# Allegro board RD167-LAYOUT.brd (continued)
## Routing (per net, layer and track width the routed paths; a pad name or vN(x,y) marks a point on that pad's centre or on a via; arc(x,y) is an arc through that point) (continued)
N15598095: length 6.9
  BOTTOM w0.5: 124,238 123.53,238.09 122.48,238.09 ; 122.48,236.82 123.17,236.82 123.45,236.55 124.23,236.55 ; 124.25,236.79 124.25,237.28 124.2,237.75
  BOTTOM w0.6: 122.48,236.82 IC10.7 ; 122.48,238.09 IC10.6
  BOTTOM w0.8: 124,238 R59.2 124.2,237.75 ; 124.25,236.79 R64.1 124.23,236.55
N15598153: length 13.4
  BOTTOM w0.45: 111.55,238.09 110.59,238.09 109.5,237 109.5,235 109.1,234.6 101.75,234.6 101.75,234.5
  BOTTOM w0.6: IC10.11 111.55,238.09
N15598155: length 21.4
  BOTTOM w0.45: 111.66,236.82 110.83,236.82 110.5,236.5 110.5,234.5 109.65,233.65 104.15,233.65 103.25,232.75 97.75,232.75 96.75,233.75 94.25,233.75
  BOTTOM w0.6: IC10.10 111.66,236.82
N16689323: length 10.2
  TOP w0.2: 146.84,56.79 146.84,55.91 147.97,54.77 147.97,53.87 ; D2.A 149.35,50 149.55,49.8 150.35,49.8 ; 148.65,52.06 148.65,53.08 C8.1 ; 148.65,51.85 148.65,50.15
  TOP w0.45: 147.97,53.87 C8.1
  TOP w0.6: IC19.5 146.84,56.79
  TOP w0.8: 150.35,49.8 R5.1 ; 148.65,50.15 D2.A ; 148.65,51.85 D3.K 148.65,52.06
N16721309: length 1.5
  TOP w0.5: 100.27,144.45 100.95,144.45 101.42,144.5
  TOP w0.8: 101.42,144.5 R32.2 ; R34.1 100.27,144.45
N16721684: length 1.5
  TOP w0.5: 100.27,194.45 100.95,194.45 101.42,194.5
  TOP w0.8: 101.42,194.5 R45.2 ; R44.1 100.27,194.45
N16722059: length 1.5
  TOP w0.5: 100.27,232.45 100.95,232.45 101.42,232.5
  TOP w0.8: 101.42,232.5 R57.2 ; R56.1 100.27,232.45
N17096693: length 88
  CONDUCTIVE2 w1: C6.1 67,80.96 ; C6.1 73.25,80.96 ; C6.1 70.04,77.75 ; C6.1 70.04,83.75 ; C3.2 62.96,58.25 ; C3.2 62.96,51.75 ; C3.2 59.75,55.04 ; C3.2 66.25,55.04 ; R2.2 62.75,22.5 ; R2.2 62.75,18.75 ; R2.2 64.5,20.5 ; R2.2 61,20.5 ; R4.1 68.75,20.5 ; R4.1 70.25,19 ; R4.1 71.75,20.5 ; R4.1 70.25,22.25 ; C4.2 93.96,52 ; C4.2 91.25,55.04 ; C4.2 97.25,55.04 ; C4.2 93.96,58 ; C2.2 29,55.04 ; C2.2 31.96,58.25 ; C2.2 35.25,55.04 ; C2.2 31.96,51.75 ; C7.1 101.04,83.75 ; C7.1 104.5,80.96 ; C7.1 101.04,77.75 ; C7.1 97.75,80.96 ; C5.1 39.04,78 ; C5.1 42,80.96 ; C5.1 36,80.96 ; C5.1 39.04,83.75
N17096799: length 7.8
  TOP w0.2: 148.12,63.08 148.12,63.53 147.9,63.75 v1(145.75,63.75)
  TOP w0.6: IC19.3 148.12,63.08
  BOTTOM w0.2: 144.55,65.1 144.55,63.9 ; 144.55,66.6 144.55,65.4 ; v1(145.75,63.75) 144.7,63.75
  BOTTOM w0.8: R9.2 144.55,66.6 ; 144.55,63.9 C12.2 144.7,63.75 ; 144.55,65.1 R8.2 144.55,65.4
N17096941: length 15
  TOP w0.2: 149.38,63.08 149.38,63.62 145.75,67.25 v1(145.75,71.75)
  TOP w0.6: IC19.2 149.38,63.08
  BOTTOM w0.2: 144.55,71.6 144.55,70.4 ; v1(145.75,71.75) 144.7,71.75 ; 144.55,70.1 144.55,68.9
  BOTTOM w0.8: 144.55,70.1 R18.2 144.55,70.4 ; 144.55,68.9 R16.2 ; 144.55,71.6 C15.2 144.7,71.75
N17096947: length 12.2
  BOTTOM w0.2: 127,66.48 D6.K 127,67.55 ; 127,65.45 D5.A 127,66.33
  BOTTOM w0.8: R14.2 123.25,65.25 123.75,65.75 R15.1 C14.1 125.72,66.48 127,66.48 ; 127,66.48 130.19,66.48 ; 127,66.48 127,66.33
  BOTTOM w1.5: IC2.2 130.19,66.48
N17096957: length 1.3
  BOTTOM w0.8: R13.2 120.25,65.25
N17096959: length 1.3
  BOTTOM w0.8: R13.1 115.75,65.25
N17096961: length 1.3
  BOTTOM w0.8: R12.1 112.5,65.25
N17096963: length 1.3
  BOTTOM w0.8: R10.2 110.5,65.25
N17107994: length 3.4
  TOP w0.3: 150,31.01 150,27.99
  TOP w0.8: 150,27.99 LED1.A ; R133.2 150,31.01
N17108111: length 5.4
  BOTTOM w0.2: 162.47,177.07 162.47,176.22 162,175.75 159.95,175.75 R144.1
  BOTTOM w0.35: IC22.14 162.47,177.07
N17108118: length 4.1
  BOTTOM w0.2: 163.12,177.07 163.12,176.12 161.8,174.8 161.15,174.8
  BOTTOM w0.35: IC22.13 163.12,177.07
  BOTTOM w0.8: 161.15,174.8 R145.1
N17110606: length 39.6
  TOP w0.2: 172.18,72.45 172.8,72.45 v1(174,71.25)
  TOP w0.35: IC24.9 172.18,72.45
  BOTTOM w0.2: v1(174,71.25) 174.25,71 174.25,39 174.75,38.5 C154.2 ; 175.45,40.15 175.45,41.35 ; 175.45,38.65 175.45,39.85
  BOTTOM w0.8: 175.45,40.15 R120.2 175.45,39.85 ; C154.2 175.45,38.65 ; 175.45,41.35 R122.2
N17110732: length 3.7
  BOTTOM w0.2: 177.2,41.5 178,41.5 178.27,41.23 180.44,41.23
  BOTTOM w0.8: 177.2,41.5 R122.1
  BOTTOM w1.5: IC20.6 180.44,41.23
N17110830: length 32.3
  TOP w0.2: 172.18,73.1 173.15,73.1 v1(175,71.25)
  TOP w0.35: IC24.10 172.18,73.1
  BOTTOM w0.2: 175.45,43.65 175.45,44.85 ; C159.2 174.75,47.2 174.75,71 v1(175,71.25) ; 175.45,45.15 175.45,46.35
  BOTTOM w0.8: 175.45,44.85 R129.2 175.45,45.15 ; R123.2 175.45,43.65 ; 175.45,46.35 C159.2
N17110836: length 3.7
  BOTTOM w0.2: 180.44,43.77 178.27,43.77 178,43.5 177.2,43.5
  BOTTOM w0.8: 177.2,43.5 R123.1
  BOTTOM w1.5: IC20.7 180.44,43.77
N17110838: length 12.2
  BOTTOM w0.2: 193,43.92 D56.A 193,44.8 ; 193,43.62 D58.K 193,42.7
  BOTTOM w0.8: 193,43.77 193,43.62 ; 193,43.77 189.81,43.77 ; 193,43.77 193,43.92 ; 193,43.77 194.28,43.77 C157.1 R131.1 196.25,44.25 197,45 R124.2
  BOTTOM w1.5: IC20.2 189.81,43.77
N17110848: length 1.6
  BOTTOM w0.8: R125.2 R124.1
N17110850: length 1.6
  BOTTOM w0.8: R126.2 R125.1
N17110852: length 1.6
  BOTTOM w0.8: R127.2 R126.1
N17110854: length 1.6
  BOTTOM w0.8: R127.1 R128.2
N17112898: length 5.6
  TOP w0.5: C85.2 222.05,256.3 221.37,255.62 221.37,255.25 ; 223.19,257 222.32,257 ; 224.58,257 223.71,257
  TOP w0.6: 221.37,255.25 IC11.7
  TOP w0.7: 223.71,257 223.19,257
  TOP w0.8: 222.32,257 C85.2 ; R70.1 224.58,257
N17112910: length 1.4
  TOP w0.5: R68.2 R69.1
N17113144: length 6.9
  BOTTOM w0.5: 196,253 196.47,252.91 197.52,252.91 ; 197.52,254.18 196.82,254.18 196.55,254.45 195.77,254.45 ; 195.75,254.21 195.75,253.72 195.8,253.25
  BOTTOM w0.6: 197.52,254.18 IC12.7 ; 197.52,252.91 IC12.6
  BOTTOM w0.8: 195.77,254.45 R75.1 195.75,254.21 ; 196,253 R71.2 195.8,253.25
N17113163: length 18.9
  TOP w0.5: v2(219.6,247) 219.6,246.1 218.2,244.7 215.55,244.7 214,246.25 211.25,246.25 209.5,248 v2(209.5,249) 206.85,249
  TOP w1.7: 206.85,249 TP23.1
  BOTTOM w0.6: IC12.14 208.91,249.09 v2(209.5,249)
N17113169: length 6.5
  TOP w1: v2(226.5,248) 226.7,247.8 228.15,247.8
  TOP w1.4: D31.A 228.15,247.8
  BOTTOM w0.8: R72.1 v2(226.5,248)
N17113250: length 13.3
  BOTTOM w0.45: 218.25,256.4 210.9,256.4 210.5,256 210.5,254 209.41,252.91 208.46,252.91
  BOTTOM w0.6: IC12.11 208.46,252.91
N17113254: length 21.4
  BOTTOM w0.45: 208.34,254.18 209.18,254.18 209.5,254.5 209.5,256.5 210.35,257.35 218.1,257.35 219,258.25 222.25,258.25 223.25,257.25 225.75,257.25
  BOTTOM w0.6: IC12.10 208.34,254.18
N17113676: length 5.6
  TOP w0.5: 221.37,217.25 221.37,217.62 222.05,218.3 C105.2 ; 222.32,219 223.19,219 ; 223.71,219 224.58,219
  TOP w0.6: 221.37,217.25 IC13.7
  TOP w0.7: 223.19,219 223.71,219
  TOP w0.8: 224.58,219 R82.1 ; C105.2 222.32,219
N17113688: length 1.4
  TOP w0.5: R80.2 R81.1
N17113930: length 6.9
  BOTTOM w0.5: 195.75,216.21 195.75,215.72 195.8,215.25 ; 195.77,216.45 196.55,216.45 196.82,216.18 197.52,216.18 ; 196,215 196.47,214.91 197.52,214.91
  BOTTOM w0.6: 197.52,216.18 IC14.7 ; 197.52,214.91 IC14.6
  BOTTOM w0.8: 195.77,216.45 R87.1 195.75,216.21 ; 196,215 R83.2 195.8,215.25
N17113949: length 18.9
  TOP w0.5: 206.85,211 v2(209.5,211) 209.5,210 211.25,208.25 214,208.25 215.55,206.7 218.2,206.7 219.6,208.1 v2(219.6,209)
  TOP w1.7: 206.85,211 TP28.1
  BOTTOM w0.6: IC14.14 208.91,211.09 v2(209.5,211)
N17113955: length 6.5
  TOP w1: v2(226.5,210) 226.7,209.8 228.15,209.8
  TOP w1.4: D37.A 228.15,209.8
  BOTTOM w0.8: R84.1 v2(226.5,210)
N17114036: length 13.3
  BOTTOM w0.45: 218.25,218.4 210.9,218.4 210.5,218 210.5,216 209.41,214.91 208.46,214.91
  BOTTOM w0.6: IC14.11 208.46,214.91
N17114040: length 21.4
  BOTTOM w0.45: 208.34,216.18 209.18,216.18 209.5,216.5 209.5,218.5 210.35,219.35 218.1,219.35 219,220.25 222.25,220.25 223.25,219.25 225.75,219.25
  BOTTOM w0.6: IC14.10 208.34,216.18
N17116296: length 5.6
  TOP w0.5: 224.58,169 223.71,169 ; 223.19,169 222.32,169 ; C117.2 222.05,168.3 221.37,167.62 221.37,167.25
  TOP w0.6: 221.37,167.25 IC15.7
  TOP w0.7: 223.71,169 223.19,169
  TOP w0.8: 222.32,169 C117.2 ; R94.1 224.58,169
N17116308: length 1.4
  TOP w0.5: R92.2 R93.1
N17116542: length 6.9
  BOTTOM w0.5: 197.52,166.18 196.82,166.18 196.55,166.45 195.77,166.45 ; 195.8,165.25 195.75,165.72 195.75,166.21 ; 197.52,164.91 196.47,164.91 196,165
  BOTTOM w0.6: 197.52,166.18 IC16.7 ; 197.52,164.91 IC16.6
  BOTTOM w0.8: 196,165 R95.2 195.8,165.25 ; 195.75,166.21 R99.1 195.77,166.45
N17116561: length 18.9
  TOP w0.5: 206.85,161 v2(209.5,161) 209.5,160 211.25,158.25 214,158.25 215.55,156.7 218.2,156.7 219.6,158.1 v2(219.6,159)
  TOP w1.7: 206.85,161 TP33.1
  BOTTOM w0.6: v2(209.5,161) 208.91,161.09 IC16.14
N17116567: length 6.5
  TOP w1: 228.15,159.8 226.7,159.8 v2(226.5,160)
  TOP w1.4: D43.A 228.15,159.8
  BOTTOM w0.8: R96.1 v2(226.5,160)
N17116648: length 13.3
  BOTTOM w0.45: 218.25,168.4 210.9,168.4 210.5,168 210.5,166 209.41,164.91 208.46,164.91
  BOTTOM w0.6: IC16.11 208.46,164.91
N17116652: length 21.4
  BOTTOM w0.45: 208.34,166.18 209.18,166.18 209.5,166.5 209.5,168.5 210.35,169.35 218.1,169.35 219,170.25 222.25,170.25 223.25,169.25 225.75,169.25
  BOTTOM w0.6: IC16.10 208.34,166.18
N17117074: length 5.6
  TOP w0.5: 221.37,129.25 221.37,129.62 222.05,130.3 C137.2 ; 223.71,131 224.58,131 ; 222.32,131 223.19,131
  TOP w0.6: 221.37,129.25 IC17.7
  TOP w0.7: 223.19,131 223.71,131
  TOP w0.8: C137.2 222.32,131 ; 224.58,131 R106.1
N17117086: length 1.4
  TOP w0.5: R105.1 R104.2
N17117328: length 6.9
  BOTTOM w0.5: 195.77,128.45 196.55,128.45 196.82,128.18 197.52,128.18 ; 195.8,127.25 195.75,127.72 195.75,128.21 ; 196,127 196.47,126.91 197.52,126.91
  BOTTOM w0.6: 197.52,128.18 IC18.7 ; 197.52,126.91 IC18.6
  BOTTOM w0.8: 196,127 R107.2 195.8,127.25 ; 195.77,128.45 R111.1 195.75,128.21
N17117347: length 18.9
  TOP w0.5: v2(219.6,121) 219.6,120.1 218.2,118.7 215.55,118.7 214,120.25 211.25,120.25 209.5,122 v2(209.5,123) 206.85,123
  TOP w1.7: 206.85,123 TP38.1
  BOTTOM w0.6: v2(209.5,123) 208.91,123.09 IC18.14
N17117353: length 6.5
  TOP w1: 228.15,121.8 226.7,121.8 v2(226.5,122)
  TOP w1.4: D49.A 228.15,121.8
  BOTTOM w0.8: R108.1 v2(226.5,122)
N17117434: length 13.3
  BOTTOM w0.45: 218.25,130.4 210.9,130.4 210.5,130 210.5,128 209.41,126.91 208.46,126.91
  BOTTOM w0.6: IC18.11 208.46,126.91
N17117438: length 21.4
  BOTTOM w0.45: 208.34,128.18 209.18,128.18 209.5,128.5 209.5,130.5 210.35,131.35 218.1,131.35 219,132.25 222.25,132.25 223.25,131.25 225.75,131.25
  BOTTOM w0.6: IC18.10 208.34,128.18
N17146611: length 43.5
  TOP w0.2: 150.46,48.2 149.45,48.2 149.25,48 148.45,48 ; R5.2 155,43.7 155,19.75 161,13.75 161,12.4
  TOP w0.8: 148.45,48 R3.2 ; R5.2 150.46,48.2
  TOP w1: CN1.1 161,12.4
N17153025: length 3.7
  BOTTOM w0.2: 142.8,66.75 141.52,66.75 141.25,66.48 139.56,66.48
  BOTTOM w0.8: R9.1 142.8,66.75
  BOTTOM w1.5: 139.56,66.48 IC2.7
N17153280: length 3.7
  BOTTOM w0.2: 139.56,69.02 141.25,69.02 141.52,68.75 142.8,68.75
  BOTTOM w0.8: R16.1 142.8,68.75
  BOTTOM w1.5: 139.56,69.02 IC2.6
N17330270: length 6.9
  TOP w0.2: 154.55,80.35 154.55,79.15 ; 154.55,77.35 154.55,76.1 155.6,75.05 156.12,75.05 ; 154.55,78.85 154.55,77.65
  TOP w0.35: IC1.13 156.12,75.05
  TOP w0.8: C168.1 154.55,80.35 ; 154.55,77.65 R153.1 154.55,77.35 ; 154.55,79.15 R155.2 154.55,78.85
N17330302: length 8.2
  TOP w0.2: 149.5,75.79 149.5,75.25 149.7,75.05 150.32,75.05 ; 149.5,75.79 150.38,75.79 ; 149.5,75.79 149.5,77 150,77.5 152.8,77.5
  TOP w0.35: IC1.2 150.32,75.05
  TOP w0.5: 150.38,75.79 IC1.1
  TOP w0.8: R153.2 152.8,77.5
N17330344: length 8.2
  TOP w0.2: 150.32,72.45 149.7,72.45 149.5,72.25 149.5,71.71 ; 149.5,71.71 149.5,70.5 150,70 152.8,70 ; 149.5,71.71 150.36,71.71
  TOP w0.35: IC1.6 150.32,72.45
  TOP w0.5: 150.36,71.71 IC1.7
  TOP w0.8: R154.2 152.8,70
N17330348: length 8.9
  TOP w0.2: 156.12,74.4 155.6,74.4 154.55,73.35 154.55,70.15 ; 154.55,68.65 154.55,69.85 ; 154.55,67.15 154.55,68.35
  TOP w0.35: IC1.12 156.12,74.4
  TOP w0.8: C170.1 154.55,67.15 ; 154.55,69.85 R154.1 154.55,70.15 ; 154.55,68.35 R156.2 154.55,68.65
N17330358: length 28.3
  TOP w0.2: 158,66 158,71.71 ; 158,66 153.25,66 152.95,66.3 152.95,66.85 ; 158,66 166.95,66 C173.2 ; 158,71.71 158,72.25 157.8,72.45 157.18,72.45 ; 158,71.71 157.09,71.71 ; 152.95,68.35 152.95,67.15 ; 167.95,68.35 167.95,67.15
  TOP w0.35: IC1.9 157.18,72.45
  TOP w0.5: 157.09,71.71 IC1.8
  TOP w0.8: 152.95,66.85 C170.2 152.95,67.15 ; R160.1 167.95,68.35 ; R156.1 152.95,68.35 ; 167.95,67.15 C173.2
N17330496: length 7
  TOP w0.2: 169.55,78.85 169.55,77.65 ; 171.12,75.05 170.55,75.05 169.55,76.05 169.55,77.35 ; 169.55,80.35 169.55,79.15
  TOP w0.35: IC24.13 171.12,75.05
  TOP w0.8: C171.1 169.55,80.35 ; 169.55,77.65 R157.1 169.55,77.35 ; 169.55,79.15 R158.2 169.55,78.85
N17330528: length 8.2
  TOP w0.2: 165.32,75.05 164.65,75.05 164.5,75.2 164.5,75.79 ; 164.5,75.79 165.36,75.79 ; 164.5,75.79 164.5,77 165,77.5 167.8,77.5
  TOP w0.35: IC24.2 165.32,75.05
  TOP w0.5: 165.36,75.79 IC24.1
  TOP w0.8: R157.2 167.8,77.5
N17330570: length 8.2
  TOP w0.2: 167.8,70 165,70 164.5,70.5 164.5,71.7 ; 165.41,71.71 164.51,71.71 164.5,71.7 ; 164.5,71.7 164.5,72.25 164.7,72.45 165.32,72.45
  TOP w0.35: IC24.6 165.32,72.45
  TOP w0.5: 165.41,71.71 IC24.7
  TOP w0.8: R159.2 167.8,70
N17330574: length 8.9
  TOP w0.2: 169.55,68.35 169.55,67.15 ; 169.55,70.15 169.55,73.35 170.6,74.4 171.12,74.4 ; 169.55,69.85 169.55,68.65
  TOP w0.35: IC24.12 171.12,74.4
  TOP w0.8: 169.55,70.15 R159.1 169.55,69.85 ; 169.55,68.65 R160.2 169.55,68.35 ; 169.55,67.15 C173.1
N17330740: length 10.3
  TOP w0.2: C175.1 162.05,74.55 161.25,73.75 161.25,72.72 ; 162.05,75.32 162.05,76.35 162.2,76.5 162.2,77.3 ; 161.15,72.5 159,72.5 158.4,73.1 157.18,73.1
  TOP w0.35: 157.18,73.1 IC1.10
  TOP w0.5: 162.2,77.3 IC23.5
  TOP w0.8: C175.1 162.05,75.32
  TOP w1.7: 161.25,72.72 TP59.1 161.15,72.5

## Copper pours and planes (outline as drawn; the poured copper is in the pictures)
+5V on TOP (solid shape): 154.97,240.21 154.81,240.74 155.33,240.92 156.13,240.55 156.36,240.19 156.13,239.83 155.33,239.46 154.81,239.64 154.97,240.17
+5V on CONDUCTIVE2: outline of 247 points within 123.8,1 196.25,252.25 ; 322 cut-outs
+12V_Q5 on TOP: 215.37,246 215.32,246.01 215.27,246.04 214.53,246.78 214.29,246.94 214,247 212.06,247 212,247.01 211.96,247.04 210.79,248.21 210.76,248.25 210.75,248.31 210.75,249.19 210.76,249.25 210.79,249.29 211.21,249.71 211.25,249.74 211.31,249.75 213.12,249.75 213.18,249.74 213.23,249.71 213.6,249.34 213.97,249.09 214.41,249 216.77,249 217.21,249.09 217.59,249.34 217.71,249.46 217.75,249.49 217.81,249.5 218.69,249.5 219.13,249.59 219.5,249.84 219.87,250.21 219.92,250.24 219.98,250.25 220.35,250.25 220.46,250.21 220.5,250.1 220.5,248.46 220.49,248.4 220.46,248.36 220.14,248.04 220.1,248.01 220.04,248 219.6,248 218.89,247.71 218.6,247 218.6,246.96 218.59,246.9 218.56,246.86 217.74,246.04 217.7,246.01 217.64,246
+12V_Q6 on TOP: 215.37,208 215.32,208.01 215.27,208.04 214.53,208.78 214.29,208.94 214,209 212.06,209 212,209.01 211.96,209.04 210.79,210.21 210.76,210.25 210.75,210.31 210.75,211.19 210.76,211.25 210.79,211.29 211.21,211.71 211.25,211.74 211.31,211.75 213.12,211.75 213.18,211.74 213.23,211.71 213.6,211.34 213.97,211.09 214.41,211 216.77,211 217.21,211.09 217.59,211.34 217.71,211.46 217.75,211.49 217.81,211.5 218.69,211.5 219.13,211.59 219.5,211.84 219.87,212.21 219.92,212.24 219.98,212.25 220.35,212.25 220.46,212.21 220.5,212.1 220.5,210.46 220.49,210.4 220.46,210.36 220.14,210.04 220.1,210.01 220.04,210 219.6,210 218.89,209.71 218.6,209 218.6,208.96 218.59,208.9 218.56,208.86 217.74,208.04 217.7,208.01 217.64,208
+12V_Q7 on TOP: 215.37,158 215.32,158.01 215.27,158.04 214.53,158.78 214.29,158.94 214,159 212.06,159 212,159.01 211.96,159.04 210.79,160.21 210.76,160.25 210.75,160.31 210.75,161.19 210.76,161.25 210.79,161.29 211.21,161.71 211.25,161.74 211.31,161.75 213.12,161.75 213.18,161.74 213.23,161.71 213.6,161.34 213.97,161.09 214.41,161 216.77,161 217.21,161.09 217.59,161.34 217.71,161.46 217.75,161.49 217.81,161.5 218.69,161.5 219.13,161.59 219.5,161.84 219.87,162.21 219.92,162.24 219.98,162.25 220.35,162.25 220.46,162.21 220.5,162.1 220.5,160.46 220.49,160.4 220.46,160.36 220.14,160.04 220.1,160.01 220.04,160 219.6,160 218.89,159.71 218.6,159 218.6,158.96 218.59,158.9 218.56,158.86 217.74,158.04 217.7,158.01 217.64,158
+12V_Q8 on TOP: 215.37,120 215.32,120.01 215.27,120.04 214.53,120.78 214.29,120.94 214,121 212.06,121 212,121.01 211.96,121.04 210.79,122.21 210.76,122.25 210.75,122.31 210.75,123.19 210.76,123.25 210.79,123.29 211.21,123.71 211.25,123.74 211.31,123.75 213.12,123.75 213.18,123.74 213.23,123.71 213.6,123.34 213.97,123.09 214.41,123 216.77,123 217.21,123.09 217.59,123.34 217.71,123.46 217.75,123.49 217.81,123.5 218.69,123.5 219.13,123.59 219.5,123.84 219.87,124.21 219.92,124.24 219.98,124.25 220.35,124.25 220.46,124.21 220.5,124.1 220.5,122.46 220.49,122.4 220.46,122.36 220.14,122.04 220.1,122.01 220.04,122 219.6,122 218.89,121.71 218.6,121 218.6,120.96 218.59,120.9 218.56,120.86 217.74,120.04 217.7,120.01 217.64,120
+20V_Q1 on TOP: 99.65,114.75 99.54,114.79 99.5,114.9 99.5,116.54 99.51,116.6 99.54,116.64 99.86,116.96 99.9,116.99 99.96,117 100.4,117 101.11,117.29 101.4,118 101.4,118.04 101.41,118.1 101.44,118.14 102.26,118.96 102.3,118.99 102.36,119 104.63,119 104.68,118.99 104.73,118.96 105.47,118.22 105.71,118.06 106,118 107.94,118 108,117.99 108.04,117.96 109.21,116.79 109.24,116.75 109.25,116.69 109.25,115.81 109.24,115.75 109.21,115.71 108.79,115.29 108.75,115.26 108.69,115.25 106.88,115.25 106.82,115.26 106.77,115.29 106.4,115.66 106.03,115.91 105.59,116 103.23,116 102.79,115.91 102.41,115.66 102.29,115.54 102.25,115.51 102.19,115.5 101.31,115.5 100.87,115.41 100.5,115.16 100.13,114.79 100.08,114.76 100.02,114.75
+20V_Q2 on TOP: 99.65,152.75 99.54,152.79 99.5,152.9 99.5,154.54 99.51,154.6 99.54,154.64 99.86,154.96 99.9,154.99 99.96,155 100.4,155 101.11,155.29 101.4,156 101.4,156.04 101.41,156.1 101.44,156.14 102.26,156.96 102.3,156.99 102.36,157 104.63,157 104.68,156.99 104.73,156.96 105.47,156.22 105.71,156.06 106,156 107.94,156 108,155.99 108.04,155.96 109.21,154.79 109.24,154.75 109.25,154.69 109.25,153.81 109.24,153.75 109.21,153.71 108.79,153.29 108.75,153.26 108.69,153.25 106.88,153.25 106.82,153.26 106.77,153.29 106.4,153.66 106.03,153.91 105.59,154 103.23,154 102.79,153.91 102.41,153.66 102.29,153.54 102.25,153.51 102.19,153.5 101.31,153.5 100.87,153.41 100.5,153.16 100.13,152.79 100.08,152.76 100.02,152.75
+20V_Q3 on TOP: 99.65,202.75 99.54,202.79 99.5,202.9 99.5,204.54 99.51,204.6 99.54,204.64 99.86,204.96 99.9,204.99 99.96,205 100.4,205 101.11,205.29 101.4,206 101.4,206.04 101.41,206.1 101.44,206.14 102.26,206.96 102.3,206.99 102.36,207 104.63,207 104.68,206.99 104.73,206.96 105.47,206.22 105.71,206.06 106,206 107.94,206 108,205.99 108.04,205.96 109.21,204.79 109.24,204.75 109.25,204.69 109.25,203.81 109.24,203.75 109.21,203.71 108.79,203.29 108.75,203.26 108.69,203.25 106.88,203.25 106.82,203.26 106.77,203.29 106.4,203.66 106.03,203.91 105.59,204 103.23,204 102.79,203.91 102.41,203.66 102.29,203.54 102.25,203.51 102.19,203.5 101.31,203.5 100.87,203.41 100.5,203.16 100.13,202.79 100.08,202.76 100.02,202.75
+20V_Q4 on TOP: 99.65,240.75 99.54,240.79 99.5,240.9 99.5,242.54 99.51,242.6 99.54,242.64 99.86,242.96 99.9,242.99 99.96,243 100.4,243 101.11,243.29 101.4,244 101.4,244.04 101.41,244.1 101.44,244.14 102.26,244.96 102.3,244.99 102.36,245 104.63,245 104.68,244.99 104.73,244.96 105.47,244.22 105.71,244.06 106,244 107.94,244 108,243.99 108.04,243.96 109.21,242.79 109.24,242.75 109.25,242.69 109.25,241.81 109.24,241.75 109.21,241.71 108.79,241.29 108.75,241.26 108.69,241.25 106.88,241.25 106.82,241.26 106.77,241.29 106.4,241.66 106.03,241.91 105.59,242 103.23,242 102.79,241.91 102.41,241.66 102.29,241.54 102.25,241.51 102.19,241.5 101.31,241.5 100.87,241.41 100.5,241.16 100.13,240.79 100.08,240.76 100.02,240.75
+24V on TOP: outline of 183 points within 186,119.35 197.4,264.73 ; 4 cut-outs
+24V on TOP: outline of 186 points within 122.6,100.28 134,245.65 ; 4 cut-outs
+24V on TOP: 164.5,251.95 164.47,251.88 164.4,251.85 159.6,251.85 159.53,251.88 159.5,251.95 159.5,254.6 159.53,254.67 159.6,254.7 164.4,254.7 164.47,254.67 164.5,254.6 ; 2 cut-outs
+24V on CONDUCTIVE2: outline of 349 points within 119.5,97.61 200.5,279.5 ; 36 cut-outs
GND on TOP (solid shape): 154.97,237.67 154.81,238.2 155.33,238.38 156.13,238.01 156.36,237.65 156.13,237.29 155.33,236.92 154.81,237.1 154.97,237.63
GND on TOP: outline of 163 points within 136,186.07 182.8,252.25
GND on TOP: 156.1,162.35 156.01,162.37 155.93,162.42 154.92,163.43 154.87,163.51 154.85,163.6 154.85,164.95 155,165.18 155.28,165.12 155.58,164.83 155.77,164.7 156,164.65 156.25,164.65 156.43,164.58 156.5,164.4 156.5,162.6 156.43,162.42 156.25,162.35
GND on TOP: outline of 497 points within 136,0.5 184,247.85 ; 13 cut-outs
GND on BOTTOM: outline of 107 points within 119.5,146 139.38,203.74
GND on BOTTOM: outline of 105 points within 119.5,196 140.88,241.74
GND on BOTTOM: outline of 106 points within 119.5,108 147.12,153.74
GND on BOTTOM: outline of 112 points within 178.12,207.13 200.5,257
GND on BOTTOM: outline of 104 points within 178.12,123.26 200.5,169
GND on BOTTOM: outline of 107 points within 168.24,161.26 200.5,219
GND on BOTTOM: outline of 984 points within 119.5,0.5 200.5,257 ; 13 cut-outs
GND on BOTTOM: 161.74,189.6 161.35,189.7 161.15,189.7 160.95,189.68 160.77,189.6 160.52,189.61 160.4,189.82 160.4,189.88 160.42,189.97 160.47,190.05 160.83,190.41 160.93,190.47 161.06,190.47 161.33,190.45 161.58,190.52 161.7,190.58 161.75,190.59 161.81,190.6 163.13,190.6 163.22,190.58 163.3,190.53 163.72,190.11 163.77,189.81 163.5,189.69 163.42,189.7 163.35,189.7 163.15,189.7 162.76,189.6 162.46,189.31 162.25,189.19 162.04,189.31
GND on CONDUCTIVE3: outline of 301 points within 123.75,1 196.25,252.25 ; 76 cut-outs
GND on CONDUCTIVE4: outline of 268 points within 123.75,1 196.25,252.25 ; 62 cut-outs
GND on CONDUCTIVE5: outline of 280 points within 123.8,1 196.25,252.25 ; 67 cut-outs
GND_24V on TOP: outline of 148 points within 192,119.35 200.5,262.25 ; 4 cut-outs
GND_24V on TOP: outline of 148 points within 119.5,102.75 128,245.65 ; 4 cut-outs
GND_24V on TOP: outline of 94 points within 119.5,246 184.38,279.75 ; 8 cut-outs
GND_24V on CONDUCTIVE3: outline of 276 points within 119.5,97.61 200.5,279.25 ; 6 cut-outs
GND_24V on CONDUCTIVE5: outline of 273 points within 119.5,97.61 200.5,279.5 ; 6 cut-outs
GND_DC_PRI on BOTTOM: 128.13,71.25 127.94,71.34 127.89,71.55 127.9,71.62 127.9,71.7 127.9,71.9 127.85,72.19 127.69,72.44 127.42,72.63 127.1,72.7 127,72.7 126.82,72.77 126.75,72.95 126.75,73.5 126.82,73.68 127,73.75 131.25,73.75 131.43,73.68 131.5,73.5 131.5,73.06 131.43,72.88 131.25,72.81 129.95,72.81 129.84,72.8 129.46,72.55 129.35,72.21 129.35,71.5 129.28,71.32 129.1,71.25
GND_DC_PRI on CONDUCTIVE5: 117.5,73.15 117.52,73.24 117.57,73.32 120.43,76.18 120.51,76.23 120.6,76.25 129.4,76.25 129.49,76.23 129.57,76.18 132.43,73.32 132.48,73.24 132.5,73.15 132.5,51.25 132.43,51.07 132.25,51 120.93,51 120.84,51.02 120.76,51.07 117.57,54.26 117.52,54.34 117.5,54.43 ; 2 cut-outs
GND_DC_SEC on BOTTOM: 188.75,36.25 188.57,36.32 188.5,36.5 188.5,37.19 188.57,37.37 188.75,37.44 190.05,37.44 190.47,37.62 190.65,38.04 190.65,39 190.72,39.18 190.9,39.25 191.85,39.25 192.03,39.18 192.1,39 192.1,38.35 192.33,37.78 192.9,37.55 193,37.55 193.18,37.48 193.25,37.3 193.25,36.53 193.19,36.37 193.04,36.29 192.95,36.27 192.81,36.25
GND_DC_SEC on CONDUCTIVE5: 187.5,61.9 187.52,61.99 187.57,62.07 190.43,64.93 190.51,64.98 190.6,65 199.4,65 199.49,64.98 199.57,64.93 202.43,62.07 202.48,61.99 202.5,61.9 202.5,41.68 202.48,41.59 202.43,41.51 197.99,37.07 197.91,37.02 197.82,37 188.85,37 188.76,37.02 188.68,37.07 187.57,38.18 187.52,38.26 187.5,38.35 ; 2 cut-outs
GND_Q1 on TOP: 112.81,104 112.75,104.01 112.71,104.04 112.29,104.46 112.26,104.5 112.25,104.56 112.25,106 105.75,112.5 104.98,112.5 104.93,112.51 104.87,112.55 104.85,112.55 104.69,112.55 104.59,112.51 104.5,112.5 103.5,112.5 103.41,112.51 103.31,112.55 103.15,112.55 103.11,112.54 103.1,112.5 103.1,112.39 103.07,112.3 103,112.25 102.79,112.04 102.75,112.01 102.69,112 101.56,112 101.5,112.01 101.46,112.04 101,112.5 96.06,112.5 96,112.51 95.96,112.54 95.79,112.71 95.76,112.75 95.75,112.81 95.75,113.44 95.76,113.5 95.79,113.54 95.96,113.71 96,113.74 96.06,113.75 100.5,113.75 101.21,114.46 101.25,114.49 101.31,114.5 102.19,114.5 102.63,114.59 103,114.84 103.12,114.96 103.17,114.99 103.23,115 105.59,115 105.65,114.99 105.69,114.96 106.06,114.59 106.44,114.34 106.88,114.25 111.44,114.25 111.5,114.24 111.54,114.21 114.46,111.29 114.49,111.25 114.5,111.19 114.5,104.56 114.49,104.5 114.46,104.46 114.04,104.04 114,104.01 113.94,104
GND_Q1 on BOTTOM: 107.7,109.35 107.59,109.39 107.55,109.5 107.55,111 107.3,111.25 106.65,111.25 106.54,111.29 106.5,111.4 106.5,114.6 106.54,114.71 106.65,114.75 106.87,114.75 107,114.74 107.13,114.75 107.94,114.75 108,114.74 108.04,114.71 108.96,113.79 108.99,113.75 109,113.69 109.03,113.63 109.1,113.6 109.19,113.6 109.22,113.6 109.32,113.64 109.4,113.65 109.6,113.65 109.68,113.64 109.78,113.6 109.81,113.6 109.9,113.6 109.95,113.62 110.05,113.73 110.13,113.75 112.1,113.75 112.21,113.71 112.25,113.6 112.25,113.15 112.21,113.04 112.1,113 110.44,113 108.97,111.53 108.81,111.29 108.75,111 108.75,109.66 108.74,109.6 108.71,109.56 108.54,109.39 108.5,109.36 108.44,109.35
GND_Q1 on CONDUCTIVE2: 95,120.85 95.04,120.96 95.15,121 104.11,121 104.17,120.99 104.22,120.96 105.59,119.59 106.23,119.15 107,119 114.35,119 114.46,118.96 114.5,118.85 114.5,106.15 114.46,106.04 114.35,106 105.41,106 105.28,106.07 105.28,106.22 104.75,107.1 104.22,106.22 104.22,106.07 104.09,106 95.15,106 95.04,106.04 95,106.15 ; 2 cut-outs
GND_Q1 on CONDUCTIVE3, CONDUCTIVE4: 114.5,106.25 114.43,106.07 114.25,106 105.56,106 105.36,106.1 105.32,106.32 104.75,107.1 104.18,106.32 104.14,106.1 103.94,106 95.25,106 95.07,106.07 95,106.25 95,120.75 95.07,120.93 95.25,121 104.07,121 104.16,120.98 104.24,120.93 105.59,119.59 106.23,119.15 107,119 114.25,119 114.43,118.93 114.5,118.75 ; 2 cut-outs
GND_Q2 on TOP: 112.81,142 112.75,142.01 112.71,142.04 112.29,142.46 112.26,142.5 112.25,142.56 112.25,144 105.75,150.5 104.98,150.5 104.93,150.51 104.87,150.55 104.85,150.55 104.69,150.55 104.59,150.51 104.5,150.5 103.5,150.5 103.41,150.51 103.31,150.55 103.15,150.55 103.11,150.54 103.1,150.5 103.1,150.39 103.07,150.3 103,150.25 102.79,150.04 102.75,150.01 102.69,150 101.56,150 101.5,150.01 101.46,150.04 101,150.5 96.06,150.5 96,150.51 95.96,150.54 95.79,150.71 95.76,150.75 95.75,150.81 95.75,151.44 95.76,151.5 95.79,151.54 95.96,151.71 96,151.74 96.06,151.75 100.5,151.75 101.21,152.46 101.25,152.49 101.31,152.5 102.19,152.5 102.63,152.59 103,152.84 103.12,152.96 103.17,152.99 103.23,153 105.59,153 105.65,152.99 105.69,152.96 106.06,152.59 106.44,152.34 106.88,152.25 111.44,152.25 111.5,152.24 111.54,152.21 114.46,149.29 114.49,149.25 114.5,149.19 114.5,142.56 114.49,142.5 114.46,142.46 114.04,142.04 114,142.01 113.94,142
GND_Q2 on BOTTOM: 107.7,147.35 107.59,147.39 107.55,147.5 107.55,149 107.3,149.25 106.65,149.25 106.54,149.29 106.5,149.4 106.5,152.6 106.54,152.71 106.65,152.75 106.87,152.75 107,152.74 107.13,152.75 107.94,152.75 108,152.74 108.04,152.71 108.96,151.79 108.99,151.75 109,151.69 109.03,151.63 109.1,151.6 109.19,151.6 109.22,151.6 109.32,151.64 109.4,151.65 109.6,151.65 109.68,151.64 109.78,151.6 109.81,151.6 109.9,151.6 109.95,151.62 110.05,151.73 110.13,151.75 112.1,151.75 112.21,151.71 112.25,151.6 112.25,151.15 112.21,151.04 112.1,151 110.44,151 108.97,149.53 108.81,149.29 108.75,149 108.75,147.66 108.74,147.6 108.71,147.56 108.54,147.39 108.5,147.36 108.44,147.35
GND_Q2 on CONDUCTIVE2: 95,158.85 95.04,158.96 95.15,159 104.11,159 104.17,158.99 104.22,158.96 105.59,157.59 106.23,157.15 107,157 114.35,157 114.46,156.96 114.5,156.85 114.5,144.15 114.46,144.04 114.35,144 105.41,144 105.28,144.07 105.28,144.22 104.75,145.1 104.22,144.22 104.22,144.07 104.09,144 95.15,144 95.04,144.04 95,144.15 ; 2 cut-outs
GND_Q2 on CONDUCTIVE3, CONDUCTIVE4: 114.5,144.25 114.43,144.07 114.25,144 105.56,144 105.36,144.1 105.32,144.32 104.75,145.1 104.18,144.32 104.14,144.1 103.94,144 95.25,144 95.07,144.07 95,144.25 95,158.75 95.07,158.93 95.25,159 104.07,159 104.16,158.98 104.24,158.93 105.59,157.59 106.23,157.15 107,157 114.25,157 114.43,156.93 114.5,156.75 ; 2 cut-outs
GND_Q3 on TOP: 112.81,192 112.75,192.01 112.71,192.04 112.29,192.46 112.26,192.5 112.25,192.56 112.25,194 105.75,200.5 104.98,200.5 104.93,200.51 104.87,200.55 104.85,200.55 104.69,200.55 104.59,200.51 104.5,200.5 103.5,200.5 103.41,200.51 103.31,200.55 103.15,200.55 103.11,200.54 103.1,200.5 103.1,200.39 103.07,200.3 103,200.25 102.79,200.04 102.75,200.01 102.69,200 101.56,200 101.5,200.01 101.46,200.04 101,200.5 96.06,200.5 96,200.51 95.96,200.54 95.79,200.71 95.76,200.75 95.75,200.81 95.75,201.44 95.76,201.5 95.79,201.54 95.96,201.71 96,201.74 96.06,201.75 100.5,201.75 101.21,202.46 101.25,202.49 101.31,202.5 102.19,202.5 102.63,202.59 103,202.84 103.12,202.96 103.17,202.99 103.23,203 105.59,203 105.65,202.99 105.69,202.96 106.06,202.59 106.44,202.34 106.88,202.25 111.44,202.25 111.5,202.24 111.54,202.21 114.46,199.29 114.49,199.25 114.5,199.19 114.5,192.56 114.49,192.5 114.46,192.46 114.04,192.04 114,192.01 113.94,192
GND_Q3 on BOTTOM: 107.7,197.35 107.59,197.39 107.55,197.5 107.55,199 107.3,199.25 106.65,199.25 106.54,199.29 106.5,199.4 106.5,202.6 106.54,202.71 106.65,202.75 106.87,202.75 107,202.74 107.13,202.75 107.94,202.75 108,202.74 108.04,202.71 108.96,201.79 108.99,201.75 109,201.69 109.03,201.63 109.1,201.6 109.19,201.6 109.22,201.6 109.32,201.64 109.4,201.65 109.6,201.65 109.68,201.64 109.78,201.6 109.81,201.6 109.9,201.6 109.95,201.62 110.05,201.73 110.13,201.75 112.1,201.75 112.21,201.71 112.25,201.6 112.25,201.15 112.21,201.04 112.1,201 110.44,201 108.97,199.53 108.81,199.29 108.75,199 108.75,197.66 108.74,197.6 108.71,197.56 108.54,197.39 108.5,197.36 108.44,197.35
GND_Q3 on CONDUCTIVE2: 95,208.85 95.04,208.96 95.15,209 104.11,209 104.17,208.99 104.22,208.96 105.59,207.59 106.23,207.15 107,207 114.35,207 114.46,206.96 114.5,206.85 114.5,194.15 114.46,194.04 114.35,194 105.41,194 105.28,194.07 105.28,194.22 104.75,195.1 104.22,194.22 104.22,194.07 104.09,194 95.15,194 95.04,194.04 95,194.15 ; 2 cut-outs
GND_Q3 on CONDUCTIVE3, CONDUCTIVE4: 114.5,194.25 114.43,194.07 114.25,194 105.56,194 105.36,194.1 105.32,194.32 104.75,195.1 104.18,194.32 104.14,194.1 103.94,194 95.25,194 95.07,194.07 95,194.25 95,208.75 95.07,208.93 95.25,209 104.07,209 104.16,208.98 104.24,208.93 105.59,207.59 106.23,207.15 107,207 114.25,207 114.43,206.93 114.5,206.75 ; 2 cut-outs
GND_Q4 on TOP: 112.81,230 112.75,230.01 112.71,230.04 112.29,230.46 112.26,230.5 112.25,230.56 112.25,232 105.75,238.5 104.98,238.5 104.93,238.51 104.87,238.55 104.85,238.55 104.69,238.55 104.59,238.51 104.5,238.5 103.5,238.5 103.41,238.51 103.31,238.55 103.15,238.55 103.11,238.54 103.1,238.5 103.1,238.39 103.07,238.3 103,238.25 102.79,238.04 102.75,238.01 102.69,238 101.56,238 101.5,238.01 101.46,238.04 101,238.5 96.06,238.5 96,238.51 95.96,238.54 95.79,238.71 95.76,238.75 95.75,238.81 95.75,239.44 95.76,239.5 95.79,239.54 95.96,239.71 96,239.74 96.06,239.75 100.5,239.75 101.21,240.46 101.25,240.49 101.31,240.5 102.19,240.5 102.63,240.59 103,240.84 103.12,240.96 103.17,240.99 103.23,241 105.59,241 105.65,240.99 105.69,240.96 106.06,240.59 106.44,240.34 106.88,240.25 111.44,240.25 111.5,240.24 111.54,240.21 114.46,237.29 114.49,237.25 114.5,237.19 114.5,230.56 114.49,230.5 114.46,230.46 114.04,230.04 114,230.01 113.94,230
GND_Q4 on BOTTOM: 107.7,235.35 107.59,235.39 107.55,235.5 107.55,237 107.3,237.25 106.65,237.25 106.54,237.29 106.5,237.4 106.5,240.6 106.54,240.71 106.65,240.75 106.87,240.75 107,240.74 107.13,240.75 107.94,240.75 108,240.74 108.04,240.71 108.96,239.79 108.99,239.75 109,239.69 109.03,239.63 109.1,239.6 109.19,239.6 109.22,239.6 109.32,239.64 109.4,239.65 109.6,239.65 109.68,239.64 109.78,239.6 109.81,239.6 109.9,239.6 109.95,239.62 110.05,239.73 110.13,239.75 112.1,239.75 112.21,239.71 112.25,239.6 112.25,239.15 112.21,239.04 112.1,239 110.44,239 108.97,237.53 108.81,237.29 108.75,237 108.75,235.66 108.74,235.6 108.71,235.56 108.54,235.39 108.5,235.36 108.44,235.35
GND_Q4 on CONDUCTIVE2: 95,246.35 95.04,246.46 95.15,246.5 104.61,246.5 104.67,246.49 104.72,246.46 105.59,245.59 105.67,245.51 105.75,245.44 106.34,245.11 107,245 114.35,245 114.46,244.96 114.5,244.85 114.5,232.15 114.46,232.04 114.35,232 105.41,232 105.28,232.07 105.28,232.22 104.75,233.1 104.22,232.22 104.22,232.07 104.09,232 95.15,232 95.04,232.04 95,232.15 ; 2 cut-outs
GND_Q4 on CONDUCTIVE3, CONDUCTIVE4: 114.5,232.25 114.43,232.07 114.25,232 105.56,232 105.36,232.1 105.32,232.32 104.75,233.1 104.18,232.32 104.14,232.1 103.94,232 95.25,232 95.07,232.07 95,232.25 95,246.25 95.07,246.43 95.25,246.5 104.57,246.5 104.66,246.48 104.74,246.43 105.59,245.59 106.23,245.15 107,245 114.25,245 114.43,244.93 114.5,244.75 ; 2 cut-outs
GND_Q5 on TOP: 214.41,250 214.35,250.01 214.31,250.04 213.94,250.41 213.56,250.66 213.12,250.75 208.56,250.75 208.5,250.76 208.46,250.79 205.54,253.71 205.51,253.75 205.5,253.81 205.5,260.44 205.51,260.5 205.54,260.54 205.96,260.96 206,260.99 206.06,261 207.19,261 207.25,260.99 207.29,260.96 207.71,260.54 207.74,260.5 207.75,260.44 207.75,257.75 211.25,254.25 212.44,254.25 212.5,254.24 212.54,254.21 214.25,252.5 215.02,252.5 215.07,252.49 215.13,252.45 215.15,252.45 215.31,252.45 215.41,252.49 215.5,252.5 216.5,252.5 216.59,252.49 216.69,252.45 216.85,252.45 216.89,252.46 216.9,252.5 216.9,252.61 216.93,252.7 217,252.75 217.21,252.96 217.25,252.99 217.31,253 218.44,253 218.5,252.99 218.54,252.96 219,252.5 223.94,252.5 224,252.49 224.04,252.46 224.21,252.29 224.24,252.25 224.25,252.19 224.25,251.56 224.24,251.5 224.21,251.46 224.04,251.29 224,251.26 223.94,251.25 219.5,251.25 218.79,250.54 218.75,250.51 218.69,250.5 217.81,250.5 217.37,250.41 217,250.16 216.88,250.04 216.83,250.01 216.77,250
GND_Q5 on BOTTOM: 212.06,250.25 212,250.26 211.96,250.29 211.04,251.21 211.01,251.25 211,251.31 210.97,251.37 210.9,251.4 210.81,251.4 210.78,251.4 210.68,251.36 210.6,251.35 210.4,251.35 210.32,251.36 210.22,251.4 210.19,251.4 210.1,251.4 210.05,251.38 209.95,251.27 209.87,251.25 207.9,251.25 207.79,251.29 207.75,251.4 207.75,251.85 207.79,251.96 207.9,252 209.56,252 211.03,253.47 211.19,253.71 211.25,254 211.25,255.34 211.26,255.4 211.29,255.44 211.46,255.61 211.5,255.64 211.56,255.65 212.3,255.65 212.41,255.61 212.45,255.5 212.45,254 212.7,253.75 213.35,253.75 213.46,253.71 213.5,253.6 213.5,250.4 213.46,250.29 213.35,250.25 213.13,250.25 213,250.26 212.87,250.25
GND_Q5 on CONDUCTIVE2: 205.65,246 205.54,246.04 205.5,246.15 205.5,258.85 205.54,258.96 205.65,259 217.09,259 217.22,258.93 217.22,258.78 217.75,257.9 218.28,258.78 218.28,258.93 218.41,259 225.31,259 225.37,258.99 225.42,258.95 225.46,258.9 225.49,258.85 225.5,258.8 225.5,244.15 225.46,244.04 225.35,244 215.89,244 215.83,244.01 215.78,244.04 214.41,245.41 213.77,245.85 213,246 ; 2 cut-outs
GND_Q5 on CONDUCTIVE3: 205.5,258.75 205.57,258.93 205.75,259 216.94,259 217.14,258.9 217.18,258.68 217.75,257.9 218.32,258.68 218.36,258.9 218.56,259 225.25,259 225.43,258.93 225.5,258.75 225.5,244.25 225.43,244.07 225.25,244 215.93,244 215.84,244.02 215.76,244.07 214.41,245.41 213.77,245.85 213,246 205.75,246 205.57,246.07 205.5,246.25 ; 2 cut-outs
GND_Q5 on CONDUCTIVE4: 225.5,244.25 225.43,244.07 225.25,244 215.93,244 215.84,244.02 215.76,244.07 214.41,245.41 213.77,245.85 213,246 205.75,246 205.57,246.07 205.5,246.25 205.5,258.75 205.57,258.93 205.75,259 216.94,259 217.14,258.9 217.18,258.68 217.75,257.9 218.32,258.68 218.36,258.9 218.56,259 225.25,259 225.43,258.93 225.5,258.75 ; 2 cut-outs
GND_Q6 on TOP: 214.41,212 214.35,212.01 214.31,212.04 213.94,212.41 213.56,212.66 213.12,212.75 208.56,212.75 208.5,212.76 208.46,212.79 205.54,215.71 205.51,215.75 205.5,215.81 205.5,222.44 205.51,222.5 205.54,222.54 205.96,222.96 206,222.99 206.06,223 207.19,223 207.25,222.99 207.29,222.96 207.71,222.54 207.74,222.5 207.75,222.44 207.75,219.75 211.25,216.25 212.44,216.25 212.5,216.24 212.54,216.21 214.25,214.5 215.02,214.5 215.07,214.49 215.13,214.45 215.15,214.45 215.31,214.45 215.41,214.49 215.5,214.5 216.5,214.5 216.59,214.49 216.69,214.45 216.85,214.45 216.89,214.46 216.9,214.5 216.9,214.61 216.93,214.7 217,214.75 217.21,214.96 217.25,214.99 217.31,215 218.44,215 218.5,214.99 218.54,214.96 219,214.5 223.94,214.5 224,214.49 224.04,214.46 224.21,214.29 224.24,214.25 224.25,214.19 224.25,213.56 224.24,213.5 224.21,213.46 224.04,213.29 224,213.26 223.94,213.25 219.5,213.25 218.79,212.54 218.75,212.51 218.69,212.5 217.81,212.5 217.37,212.41 217,212.16 216.88,212.04 216.83,212.01 216.77,212
GND_Q6 on BOTTOM: 212.06,212.25 212,212.26 211.96,212.29 211.04,213.21 211.01,213.25 211,213.31 210.97,213.37 210.9,213.4 210.81,213.4 210.78,213.4 210.68,213.36 210.6,213.35 210.4,213.35 210.32,213.36 210.22,213.4 210.19,213.4 210.1,213.4 210.05,213.38 209.95,213.27 209.87,213.25 207.9,213.25 207.79,213.29 207.75,213.4 207.75,213.85 207.79,213.96 207.9,214 209.56,214 211.03,215.47 211.19,215.71 211.25,216 211.25,217.34 211.26,217.4 211.29,217.44 211.46,217.61 211.5,217.64 211.56,217.65 212.3,217.65 212.41,217.61 212.45,217.5 212.45,216 212.7,215.75 213.35,215.75 213.46,215.71 213.5,215.6 213.5,212.4 213.46,212.29 213.35,212.25 213.13,212.25 213,212.26 212.87,212.25
GND_Q6 on CONDUCTIVE2: 225.5,206.15 225.46,206.04 225.35,206 215.89,206 215.83,206.01 215.78,206.04 214.41,207.41 213.77,207.85 213,208 205.65,208 205.54,208.04 205.5,208.15 205.5,220.85 205.54,220.96 205.65,221 217.09,221 217.22,220.93 217.22,220.78 217.75,219.9 218.28,220.78 218.28,220.93 218.41,221 225.35,221 225.46,220.96 225.5,220.85 ; 2 cut-outs
GND_Q6 on CONDUCTIVE3, CONDUCTIVE4: 205.5,220.75 205.57,220.93 205.75,221 216.94,221 217.14,220.9 217.18,220.68 217.75,219.9 218.32,220.68 218.36,220.9 218.56,221 225.25,221 225.43,220.93 225.5,220.75 225.5,206.25 225.43,206.07 225.25,206 215.93,206 215.84,206.02 215.76,206.07 214.41,207.41 213.77,207.85 213,208 205.75,208 205.57,208.07 205.5,208.25 ; 2 cut-outs
GND_Q7 on TOP: 214.41,162 214.35,162.01 214.31,162.04 213.94,162.41 213.56,162.66 213.12,162.75 208.56,162.75 208.5,162.76 208.46,162.79 205.54,165.71 205.51,165.75 205.5,165.81 205.5,172.44 205.51,172.5 205.54,172.54 205.96,172.96 206,172.99 206.06,173 207.19,173 207.25,172.99 207.29,172.96 207.71,172.54 207.74,172.5 207.75,172.44 207.75,169.75 211.25,166.25 212.44,166.25 212.5,166.24 212.54,166.21 214.25,164.5 215.02,164.5 215.07,164.49 215.13,164.45 215.15,164.45 215.31,164.45 215.41,164.49 215.5,164.5 216.5,164.5 216.59,164.49 216.69,164.45 216.85,164.45 216.89,164.46 216.9,164.5 216.9,164.61 216.93,164.7 217,164.75 217.21,164.96 217.25,164.99 217.31,165 218.44,165 218.5,164.99 218.54,164.96 219,164.5 223.94,164.5 224,164.49 224.04,164.46 224.21,164.29 224.24,164.25 224.25,164.19 224.25,163.56 224.24,163.5 224.21,163.46 224.04,163.29 224,163.26 223.94,163.25 219.5,163.25 218.79,162.54 218.75,162.51 218.69,162.5 217.81,162.5 217.37,162.41 217,162.16 216.88,162.04 216.83,162.01 216.77,162
GND_Q7 on BOTTOM: 212.06,162.25 212,162.26 211.96,162.29 211.04,163.21 211.01,163.25 211,163.31 210.97,163.37 210.9,163.4 210.81,163.4 210.78,163.4 210.68,163.36 210.6,163.35 210.4,163.35 210.32,163.36 210.22,163.4 210.19,163.4 210.1,163.4 210.05,163.38 209.95,163.27 209.87,163.25 207.9,163.25 207.79,163.29 207.75,163.4 207.75,163.85 207.79,163.96 207.9,164 209.56,164 211.03,165.47 211.19,165.71 211.25,166 211.25,167.34 211.26,167.4 211.29,167.44 211.46,167.61 211.5,167.64 211.56,167.65 212.3,167.65 212.41,167.61 212.45,167.5 212.45,166 212.7,165.75 213.35,165.75 213.46,165.71 213.5,165.6 213.5,162.4 213.46,162.29 213.35,162.25 213.13,162.25 213,162.26 212.87,162.25
GND_Q7 on CONDUCTIVE2: 205.65,158 205.54,158.04 205.5,158.15 205.5,170.85 205.54,170.96 205.65,171 217.09,171 217.22,170.93 217.22,170.78 217.75,169.9 218.28,170.78 218.28,170.93 218.41,171 225.31,171 225.37,170.99 225.42,170.95 225.46,170.9 225.49,170.85 225.5,170.8 225.5,156.15 225.46,156.04 225.35,156 215.89,156 215.83,156.01 215.78,156.04 214.41,157.41 213.77,157.85 213,158 ; 2 cut-outs
GND_Q7 on CONDUCTIVE3, CONDUCTIVE4: 205.5,170.75 205.57,170.93 205.75,171 216.94,171 217.14,170.9 217.18,170.68 217.75,169.9 218.32,170.68 218.36,170.9 218.56,171 225.25,171 225.43,170.93 225.5,170.75 225.5,156.25 225.43,156.07 225.25,156 215.93,156 215.84,156.02 215.76,156.07 214.41,157.41 213.77,157.85 213,158 205.75,158 205.57,158.07 205.5,158.25 ; 2 cut-outs
GND_Q8 on TOP: 214.41,124 214.35,124.01 214.31,124.04 213.94,124.41 213.56,124.66 213.12,124.75 208.56,124.75 208.5,124.76 208.46,124.79 205.54,127.71 205.51,127.75 205.5,127.81 205.5,134.44 205.51,134.5 205.54,134.54 205.96,134.96 206,134.99 206.06,135 207.19,135 207.25,134.99 207.29,134.96 207.71,134.54 207.74,134.5 207.75,134.44 207.75,131.78 211.25,128.28 212.41,128.28 212.47,128.26 212.52,128.23 214.25,126.5 215.02,126.5 215.07,126.49 215.13,126.45 215.15,126.45 215.31,126.45 215.41,126.49 215.5,126.5 216.5,126.5 216.59,126.49 216.69,126.45 216.85,126.45 216.89,126.46 216.9,126.5 216.9,126.61 216.93,126.7 217,126.75 217.21,126.96 217.25,126.99 217.31,127 218.44,127 218.5,126.99 218.54,126.96 219,126.5 223.94,126.5 224,126.49 224.04,126.46 224.21,126.29 224.24,126.25 224.25,126.19 224.25,125.56 224.24,125.5 224.21,125.46 224.04,125.29 224,125.26 223.94,125.25 219.5,125.25 218.79,124.54 218.75,124.51 218.69,124.5 217.81,124.5 217.37,124.41 217,124.16 216.88,124.04 216.83,124.01 216.77,124
GND_Q8 on BOTTOM: 212.06,124.25 212,124.26 211.96,124.29 211.04,125.21 211.01,125.25 211,125.31 210.97,125.37 210.9,125.4 210.81,125.4 210.78,125.4 210.68,125.36 210.6,125.35 210.4,125.35 210.32,125.36 210.22,125.4 210.19,125.4 210.1,125.4 210.05,125.38 209.95,125.27 209.87,125.25 207.9,125.25 207.79,125.29 207.75,125.4 207.75,125.85 207.79,125.96 207.9,126 209.56,126 211.03,127.47 211.19,127.71 211.25,128 211.25,129.34 211.26,129.4 211.29,129.44 211.46,129.61 211.5,129.64 211.56,129.65 212.3,129.65 212.41,129.61 212.45,129.5 212.45,128 212.7,127.75 213.35,127.75 213.46,127.71 213.5,127.6 213.5,124.4 213.46,124.29 213.35,124.25 213.13,124.25 213,124.26 212.87,124.25
GND_Q8 on CONDUCTIVE2: 225.5,118.65 225.46,118.54 225.35,118.5 215.39,118.5 215.33,118.51 215.28,118.54 214.41,119.41 214.35,119.48 214.28,119.54 213.68,119.88 213,120 205.65,120 205.54,120.04 205.5,120.15 205.5,132.85 205.54,132.96 205.65,133 217.09,133 217.22,132.93 217.22,132.78 217.75,131.9 218.28,132.78 218.28,132.93 218.41,133 225.35,133 225.46,132.96 225.5,132.85 ; 2 cut-outs
GND_Q8 on CONDUCTIVE3, CONDUCTIVE4: 205.5,132.75 205.57,132.93 205.75,133 216.94,133 217.14,132.9 217.18,132.68 217.75,131.9 218.32,132.68 218.36,132.9 218.56,133 225.25,133 225.43,132.93 225.5,132.75 225.5,118.75 225.43,118.57 225.25,118.5 215.43,118.5 215.34,118.52 215.26,118.57 214.41,119.41 213.77,119.85 213,120 205.75,120 205.57,120.07 205.5,120.25 ; 2 cut-outs
HV_DC_N on BOTTOM (solid shape): 32.24,88.45 32.1,89.14 32.8,89.28 34.04,88.45 34.26,88.04 34.04,87.62 32.8,86.79 32.28,86.76 32.02,87.2 32.08,87.44 32.24,87.62 32.33,87.68 32.33,88.39
HV_DC_N on BOTTOM (solid shape): 63.24,88.45 63.1,89.14 63.8,89.28 65.04,88.45 65.26,88.04 65.04,87.62 63.8,86.79 63.28,86.76 63.02,87.2 63.08,87.44 63.24,87.62 63.33,87.68 63.33,88.39
HV_DC_N on BOTTOM (solid shape): 94.24,88.45 94.1,89.14 94.8,89.28 96.04,88.45 96.26,88.04 96.04,87.62 94.8,86.79 94.28,86.76 94.02,87.2 94.08,87.44 94.24,87.62 94.33,87.68 94.33,88.39
HV_DC_N on BOTTOM (solid shape): 31.76,89.22 31.91,88.87 31.85,88.63 31.69,88.45 31.6,88.39 31.6,87.68 31.69,87.62 31.82,86.93 31.13,86.79 29.89,87.62 29.66,88.04 29.89,88.45 31.13,89.28 31.26,89.35 31.41,89.37
HV_DC_N on BOTTOM (solid shape): 31.55,90.11 31.96,90.34 32.38,90.11 33.21,88.87 33.27,88.74 33.3,88.59 33.15,88.24 32.8,88.09 32.56,88.15 32.38,88.31 32.32,88.4 31.61,88.4 31.55,88.31 30.86,88.18 30.72,88.87
HV_DC_N on BOTTOM (solid shape): 62.76,89.22 62.91,88.87 62.85,88.63 62.69,88.45 62.6,88.39 62.6,87.68 62.69,87.62 62.82,86.93 62.13,86.79 60.89,87.62 60.66,88.04 60.89,88.45 62.13,89.28 62.26,89.35 62.41,89.37
HV_DC_N on BOTTOM (solid shape): 62.55,90.11 62.96,90.34 63.38,90.11 64.21,88.87 64.27,88.74 64.3,88.59 64.15,88.24 63.8,88.09 63.56,88.15 63.38,88.31 63.32,88.4 62.61,88.4 62.55,88.31 61.86,88.18 61.72,88.87
HV_DC_N on BOTTOM (solid shape): 93.76,89.22 93.91,88.87 93.85,88.63 93.69,88.45 93.6,88.39 93.6,87.68 93.69,87.62 93.82,86.93 93.13,86.79 91.89,87.62 91.66,88.04 91.89,88.45 93.13,89.28 93.26,89.35 93.41,89.37
HV_DC_N on BOTTOM (solid shape): 93.55,90.11 93.96,90.34 94.38,90.11 95.21,88.87 95.27,88.74 95.3,88.59 95.15,88.24 94.8,88.09 94.56,88.15 94.38,88.31 94.32,88.4 93.61,88.4 93.55,88.31 92.86,88.18 92.72,88.87
HV_DC_N on CONDUCTIVE3 (solid shape): 32.18,88.37 32.02,89.06 32.71,89.22 33.91,88.46 34.14,88.04 33.91,87.61 32.71,86.85 32.02,87.01 32.18,87.7 32.25,87.74 32.25,88.33
HV_DC_N on CONDUCTIVE3 (solid shape): 62.21,89.22 62.9,89.06 62.75,88.37 62.68,88.33 62.68,87.74 62.75,87.7 62.9,87.01 62.21,86.85 61.02,87.61 60.78,88.04 61.02,88.46
HV_DC_N on CONDUCTIVE3 (solid shape): 63.18,88.37 63.02,89.06 63.71,89.22 64.91,88.46 65.14,88.04 64.91,87.61 63.71,86.85 63.02,87.01 63.18,87.7 63.25,87.74 63.25,88.33
HV_DC_N on CONDUCTIVE3 (solid shape): 31.54,89.98 31.96,90.22 32.39,89.98 33.15,88.79 33.2,88.66 33.22,88.52 33.08,88.16 32.72,88.02 32.48,88.08 32.3,88.25 32.26,88.32 31.67,88.32 31.63,88.25 30.94,88.1 30.78,88.79
HV_DC_N on CONDUCTIVE3 (solid shape): 62.54,89.98 62.96,90.22 63.39,89.98 64.15,88.79 64.2,88.66 64.22,88.52 64.08,88.16 63.72,88.02 63.48,88.08 63.3,88.25 63.26,88.32 62.67,88.32 62.63,88.25 61.94,88.1 61.78,88.79
HV_DC_N on CONDUCTIVE3 (solid shape): 93.54,89.98 93.96,90.22 94.39,89.98 95.15,88.79 95.2,88.66 95.22,88.52 95.08,88.16 94.72,88.02 94.48,88.08 94.3,88.25 94.26,88.32 93.67,88.32 93.63,88.25 92.94,88.1 92.78,88.79
HV_DC_N on CONDUCTIVE3 (solid shape): 94.18,88.37 94.02,89.06 94.71,89.22 95.91,88.46 96.14,88.04 95.91,87.61 94.71,86.85 94.02,87.01 94.18,87.7 94.25,87.74 94.25,88.33
HV_DC_N on TOP: 50.5,104.25 50.43,104.07 50.25,104 45.68,104 45.52,104.06 45.44,104.21 43.78,106.78 40.79,107.44 40.59,107.49 40.5,107.68 40.5,169.32 40.59,169.51 40.79,169.56 45.5,173.5 40.79,177.44 40.59,177.49 40.5,177.68 40.5,187.32 40.59,187.51 40.79,187.56 45.5,191.5 40.79,195.44 40.59,195.49 40.5,195.68 40.5,247.5 40.57,247.68 40.75,247.75 50.25,247.75 50.43,247.68 50.5,247.5 ; 12 cut-outs
HV_DC_N on BOTTOM: outline of 403 points within 0.5,0.5 123,264.75 ; 34 cut-outs
HV_DC_N on CONDUCTIVE3: 115.66,11.71 113.5,5 113.5,4.1 113.48,4.01 113.43,3.93 110.57,1.07 110.49,1.02 110.4,1 61.5,1 61.41,1.02 61.33,1.07 58.47,3.93 58.42,4.01 58.4,4.1 58.4,12 56.89,15.58 53.26,17 53.23,17 42.69,17 39.1,15.57 37.6,12 37.6,4.1 37.58,4.01 37.53,3.93 34.67,1.07 34.59,1.02 34.5,1 19.6,1 19.51,1.02 19.43,1.07 16.57,3.93 16.52,4.01 16.5,4.1 16.5,5 13.13,13.13 5,16.5 4.1,16.5 4.01,16.52 3.93,16.57 1.07,19.43 1.02,19.51 1,19.6 1,89.65 1.02,89.74 1.07,89.82 6.18,94.93 6.26,94.98 6.35,95 103.65,95 103.74,94.98 103.82,94.93 116.54,82.21 116.87,81.87 121.43,77.32 121.48,77.24 121.5,77.15 121.5,16.14 121.45,15.99 121.33,15.9 ; 25 cut-outs
HV_DC_N on CONDUCTIVE5: outline of 152 points within 83,230 114.5,247 ; 6 cut-outs
HV_DC_N on CONDUCTIVE5: outline of 145 points within 83,142 114.5,159 ; 6 cut-outs
HV_DC_P on BOTTOM (solid shape): 100.72,50.01 101.04,50.16 101.35,50.01 102.22,48.88 102.27,48.46 101.91,48.24 101.73,48.28 101.59,48.39 101.49,48.52 100.58,48.52 100.48,48.39 99.92,48.32 99.85,48.88
HV_DC_P on CONDUCTIVE5 (solid shape): 38.14,47.96 38.7,47.75 38.74,47.68 39.33,47.68 39.37,47.75 40.06,47.9 40.22,47.21 39.46,46.02 39.04,45.78 38.61,46.02 37.85,47.21 37.8,47.34 37.78,47.48
HV_DC_P on CONDUCTIVE5 (solid shape): 38.29,49.15 38.98,48.99 38.82,48.3 38.75,48.26 38.75,47.67 38.82,47.63 38.98,46.94 38.29,46.78 37.09,47.54 36.86,47.96 37.09,48.39
HV_DC_P on CONDUCTIVE5 (solid shape): 39.25,48.3 39.1,48.99 39.79,49.15 40.98,48.39 41.22,47.96 40.98,47.54 39.79,46.78 39.1,46.94 39.25,47.63 39.32,47.67 39.32,48.26
HV_DC_P on CONDUCTIVE5 (solid shape): 69.14,47.96 69.7,47.75 69.74,47.68 70.33,47.68 70.37,47.75 71.06,47.9 71.22,47.21 70.46,46.02 70.04,45.78 69.61,46.02 68.85,47.21 68.8,47.34 68.78,47.48
HV_DC_P on CONDUCTIVE5 (solid shape): 69.29,49.15 69.98,48.99 69.82,48.3 69.75,48.26 69.75,47.67 69.82,47.63 69.98,46.94 69.29,46.78 68.09,47.54 67.86,47.96 68.09,48.39
HV_DC_P on CONDUCTIVE5 (solid shape): 70.25,48.3 70.1,48.99 70.79,49.15 71.98,48.39 72.22,47.96 71.98,47.54 70.79,46.78 70.1,46.94 70.25,47.63 70.32,47.67 70.32,48.26
HV_DC_P on CONDUCTIVE5 (solid shape): 100.14,47.96 100.7,47.75 100.74,47.68 101.33,47.68 101.37,47.75 102.06,47.9 102.22,47.21 101.46,46.02 101.04,45.78 100.61,46.02 99.85,47.21 99.8,47.34 99.78,47.48
HV_DC_P on CONDUCTIVE5 (solid shape): 101.25,48.3 101.1,48.99 101.79,49.15 102.98,48.39 103.22,47.96 102.98,47.54 101.79,46.78 101.1,46.94 101.25,47.63 101.32,47.67 101.32,48.26
HV_DC_P on CONDUCTIVE5 (solid shape): 38.61,49.91 39.04,50.14 39.46,49.91 40.22,48.71 40.28,48.59 40.3,48.45 40.15,48.09 39.8,47.95 39.55,48.01 39.37,48.18 39.33,48.25 38.74,48.25 38.7,48.18 38.01,48.02 37.85,48.71
HV_DC_P on CONDUCTIVE5 (solid shape): 69.61,49.91 70.04,50.14 70.46,49.91 71.22,48.71 71.28,48.59 71.3,48.45 71.15,48.09 70.8,47.95 70.55,48.01 70.37,48.18 70.33,48.25 69.74,48.25 69.7,48.18 69.01,48.02 68.85,48.71
HV_DC_P on CONDUCTIVE5 (solid shape): 100.61,49.91 101.04,50.14 101.46,49.91 102.22,48.71 102.28,48.59 102.3,48.45 102.15,48.09 101.8,47.95 101.55,48.01 101.37,48.18 101.33,48.25 100.74,48.25 100.7,48.18 100.01,48.02 99.85,48.71
HV_DC_P on TOP: outline of 88 points within 72.5,104.25 85,244.5 ; 10 cut-outs
